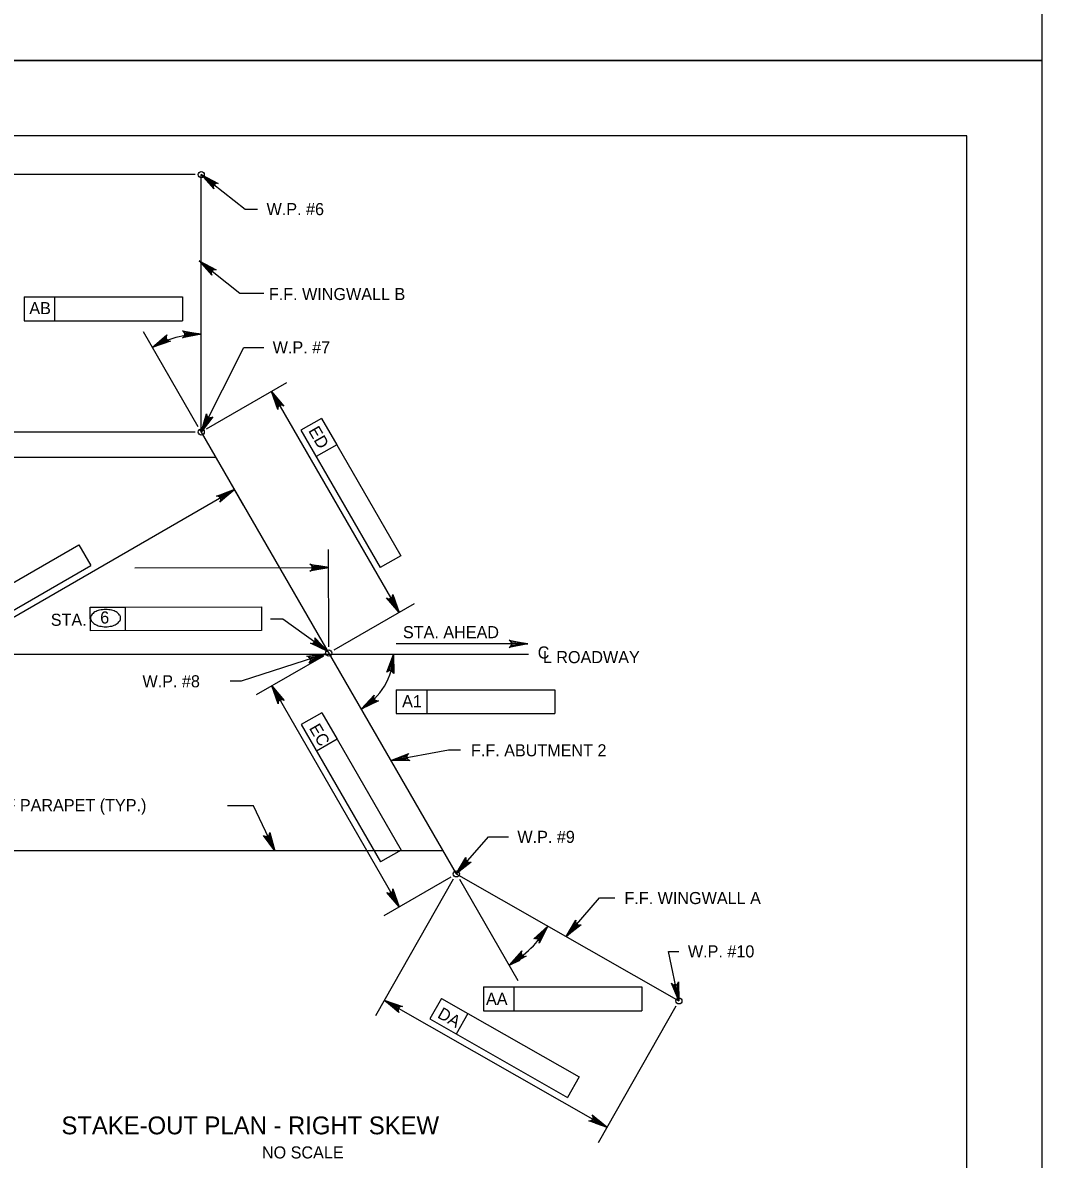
# Model space of a CAD drawing. Extents: x 0 to 36.3, y -66 to 0.
# Drawn here: x 23.87 to 34, y -32.92 to -21.62 of the extents above; entities that cross this region are included whole.
import ezdxf

# ---------------------------------------------------------------- set-up
doc = ezdxf.new("R2010")
doc.units = 0
for name, color, linetype in [('1', 7, 'Continuous'), ('2', 7, 'Continuous'), ('3', 7, 'Continuous'), ('4', 7, 'Continuous'), ('62', 7, 'Continuous'), ('63', 7, 'Continuous')]:
    doc.layers.add(name, color=color, linetype=linetype)

msp = doc.modelspace()

# ---------------------------------------------------------------- linework, layer by layer
at = {"layer": '1'}
msp.add_lwpolyline([(1.75, -43.25), (33.25, -43.25), (33.25, -22.75), (1.75, -22.75)], close=True, dxfattribs=at)
at = {"layer": '2'}
for p, q in [((25.644, -25.693), (25.644, -23.134)), ((25.644, -25.693), (28.178, -30.083)), ((25.791, -25.947), (20.486, -25.947)), ((28.046, -29.854), (21.35, -29.854)), ((28.178, -30.083), (30.39, -31.345))]:
    msp.add_line(p, q, dxfattribs=at)
at = {"layer": '3'}
msp.add_line((28.894, -27.903), (21.637, -27.903), dxfattribs=at)
for centre in [(25.644, -23.134), (25.644, -25.693), (26.911, -27.888), (28.178, -30.083), (30.39, -31.345)]:
    msp.add_circle(centre, 0.0304, dxfattribs=at)
at = {"layer": '4'}
for p, q in [((25.582, -23.134), (23.563, -23.134)), ((23.884, -24.349), (24.187, -24.349)), ((23.884, -24.349), (23.884, -24.586)), ((24.187, -24.349), (24.187, -24.586)), ((24.187, -24.349), (25.459, -24.349)), ((25.459, -24.349), (25.459, -24.586)), ((26.028, -24.312), (26.266, -24.312)), ((23.884, -24.586), (25.459, -24.586)), ((25.613, -25.64), (25.069, -24.697)), ((25.697, -25.662), (26.495, -25.201)), ((26.342, -25.29), (27.609, -27.485)), ((26.839, -25.557), (26.635, -25.675)), ((26.839, -25.557), (26.991, -25.819)), ((25.582, -25.693), (23.563, -25.693)), ((25.625, -25.661), (26.062, -26.418)), ((26.635, -25.675), (27.422, -27.039)), ((26.991, -25.819), (26.786, -25.937)), ((26.991, -25.819), (27.627, -26.921)), ((21.921, -28.605), (25.974, -26.265)), ((23.328, -27.449), (24.429, -26.813)), ((24.429, -26.813), (24.547, -27.017)), ((26.911, -27.826), (26.909, -26.861)), ((27.627, -26.921), (27.422, -27.039)), ((23.184, -27.805), (24.547, -27.017)), ((24.985, -27.042), (26.91, -27.039)), ((24.542, -27.431), (24.891, -27.431)), ((24.543, -27.667), (24.542, -27.431)), ((24.891, -27.431), (26.243, -27.429)), ((24.892, -27.667), (24.891, -27.431)), ((26.243, -27.429), (26.243, -27.666)), ((26.964, -27.857), (27.762, -27.396)), ((26.453, -27.551), (26.333, -27.551)), ((26.902, -27.872), (26.453, -27.551)), ((26.243, -27.666), (24.543, -27.667)), ((28.89, -27.797), (27.579, -27.797)), ((26.858, -27.919), (26.191, -28.304)), ((26.344, -28.215), (27.611, -30.411)), ((27.582, -28.253), (27.884, -28.253)), ((27.582, -28.253), (27.582, -28.489)), ((27.884, -28.253), (27.884, -28.489)), ((27.884, -28.253), (29.156, -28.253)), ((29.156, -28.253), (29.156, -28.489)), ((26.842, -28.482), (26.637, -28.6)), ((26.842, -28.482), (26.993, -28.744)), ((27.582, -28.489), (29.156, -28.489)), ((26.637, -28.6), (27.425, -29.964)), ((26.993, -28.744), (26.788, -28.862)), ((26.993, -28.744), (27.629, -29.846)), ((27.528, -28.956), (28.101, -28.85)), ((28.101, -28.85), (28.221, -28.85)), ((26.163, -29.408), (25.906, -29.408)), ((27.629, -29.846), (27.425, -29.964)), ((28.148, -30.137), (27.375, -31.492)), ((28.125, -30.114), (27.458, -30.499)), ((28.209, -30.136), (28.79, -31.143)), ((29.601, -30.322), (29.753, -30.322)), ((28.447, -31.206), (28.75, -31.206)), ((28.447, -31.206), (28.447, -31.443)), ((28.75, -31.206), (28.75, -31.443)), ((28.75, -31.206), (30.022, -31.206)), ((30.022, -31.206), (30.022, -31.443)), ((27.462, -31.338), (29.674, -32.6)), ((28.032, -31.32), (27.915, -31.525)), ((28.032, -31.32), (28.294, -31.47)), ((28.294, -31.47), (28.177, -31.675)), ((28.294, -31.47), (29.4, -32.101)), ((28.447, -31.443), (30.022, -31.443)), ((30.359, -31.399), (29.586, -32.754)), ((27.915, -31.525), (29.283, -32.306)), ((29.4, -32.101), (29.283, -32.306))]:
    msp.add_line(p, q, dxfattribs=at)
for points in [[(25.644, -23.134), (26.081, -23.477), (26.204, -23.477)], [(25.644, -23.134), (25.812, -23.221), (25.794, -23.22), (25.781, -23.226), (25.772, -23.234), (25.765, -23.245), (25.764, -23.26), (25.769, -23.276), (25.644, -23.134), (25.764, -23.26), (25.765, -23.245), (25.644, -23.134), (25.772, -23.234), (25.781, -23.226), (25.644, -23.134), (25.794, -23.22)], [(25.624, -23.991), (26.028, -24.312)], [(25.624, -23.991), (25.791, -24.08), (25.774, -24.079), (25.76, -24.084), (25.751, -24.092), (25.745, -24.104), (25.743, -24.118), (25.748, -24.135), (25.624, -23.991), (25.743, -24.118), (25.745, -24.104), (25.624, -23.991), (25.751, -24.092), (25.76, -24.084), (25.624, -23.991), (25.774, -24.079)], [(25.158, -24.851), (25.302, -24.727), (25.294, -24.743), (25.294, -24.758), (25.298, -24.77), (25.306, -24.779), (25.319, -24.787), (25.337, -24.788), (25.158, -24.851), (25.319, -24.787), (25.306, -24.779), (25.158, -24.851), (25.298, -24.77), (25.294, -24.758), (25.158, -24.851), (25.294, -24.743)], [(25.644, -24.721), (25.457, -24.756), (25.472, -24.746), (25.479, -24.733), (25.481, -24.721), (25.479, -24.708), (25.472, -24.696), (25.457, -24.686), (25.644, -24.721), (25.472, -24.696), (25.479, -24.708), (25.644, -24.721), (25.481, -24.721), (25.479, -24.733), (25.644, -24.721), (25.472, -24.746)], [(25.644, -25.693), (26.067, -24.851), (26.265, -24.851)], [(26.342, -25.29), (26.465, -25.434), (26.449, -25.426), (26.435, -25.426), (26.423, -25.431), (26.413, -25.439), (26.406, -25.451), (26.405, -25.469), (26.342, -25.29), (26.406, -25.451), (26.413, -25.439), (26.342, -25.29), (26.423, -25.431), (26.435, -25.426), (26.342, -25.29), (26.449, -25.426)], [(25.644, -25.693), (25.696, -25.511), (25.699, -25.528), (25.706, -25.54), (25.717, -25.548), (25.729, -25.551), (25.743, -25.55), (25.759, -25.542), (25.644, -25.693), (25.743, -25.55), (25.729, -25.551), (25.644, -25.693), (25.717, -25.548), (25.706, -25.54), (25.644, -25.693), (25.699, -25.528)], [(25.974, -26.265), (25.83, -26.388), (25.837, -26.372), (25.837, -26.358), (25.833, -26.346), (25.825, -26.336), (25.812, -26.329), (25.795, -26.328), (25.974, -26.265), (25.812, -26.329), (25.825, -26.336), (25.974, -26.265), (25.833, -26.346), (25.837, -26.358), (25.974, -26.265), (25.837, -26.372)], [(26.91, -27.039), (26.723, -27.074), (26.738, -27.064), (26.745, -27.051), (26.747, -27.039), (26.745, -27.026), (26.738, -27.014), (26.723, -27.004), (26.91, -27.039), (26.738, -27.014), (26.745, -27.026), (26.91, -27.039), (26.747, -27.039), (26.745, -27.051), (26.91, -27.039), (26.738, -27.064)], [(27.609, -27.485), (27.485, -27.341), (27.501, -27.349), (27.516, -27.349), (27.528, -27.344), (27.537, -27.336), (27.545, -27.324), (27.546, -27.306), (27.609, -27.485), (27.545, -27.324), (27.537, -27.336), (27.609, -27.485), (27.528, -27.344), (27.516, -27.349), (27.609, -27.485), (27.501, -27.349)], [(26.902, -27.872), (26.73, -27.792), (26.748, -27.793), (26.761, -27.787), (26.77, -27.778), (26.775, -27.767), (26.777, -27.752), (26.771, -27.736), (26.902, -27.872), (26.777, -27.752), (26.775, -27.767), (26.902, -27.872), (26.77, -27.778), (26.761, -27.787), (26.902, -27.872), (26.748, -27.793)], [(28.89, -27.797), (28.704, -27.832), (28.718, -27.822), (28.725, -27.809), (28.727, -27.797), (28.725, -27.784), (28.718, -27.772), (28.704, -27.762), (28.89, -27.797), (28.718, -27.772), (28.725, -27.784), (28.89, -27.797), (28.727, -27.797), (28.725, -27.809), (28.89, -27.797), (28.718, -27.822)], [(26.882, -27.897), (26.039, -28.169), (25.93, -28.169)], [(26.882, -27.897), (26.715, -27.988), (26.726, -27.974), (26.729, -27.96), (26.727, -27.947), (26.722, -27.936), (26.711, -27.927), (26.694, -27.921), (26.882, -27.897), (26.711, -27.927), (26.722, -27.936), (26.882, -27.897), (26.727, -27.947), (26.729, -27.96), (26.882, -27.897), (26.726, -27.974)], [(27.555, -27.903), (27.556, -28.093), (27.549, -28.077), (27.538, -28.067), (27.526, -28.063), (27.513, -28.063), (27.5, -28.068), (27.487, -28.08), (27.555, -27.903), (27.5, -28.068), (27.513, -28.063), (27.555, -27.903), (27.526, -28.063), (27.538, -28.067), (27.555, -27.903), (27.549, -28.077)], [(26.344, -28.215), (26.468, -28.359), (26.452, -28.352), (26.437, -28.352), (26.425, -28.356), (26.416, -28.364), (26.408, -28.377), (26.407, -28.394), (26.344, -28.215), (26.408, -28.377), (26.416, -28.364), (26.344, -28.215), (26.425, -28.356), (26.437, -28.352), (26.344, -28.215), (26.452, -28.352)], [(27.233, -28.446), (27.363, -28.308), (27.357, -28.325), (27.359, -28.339), (27.364, -28.35), (27.374, -28.359), (27.387, -28.365), (27.404, -28.364), (27.233, -28.446), (27.387, -28.365), (27.374, -28.359), (27.233, -28.446), (27.364, -28.35), (27.359, -28.339), (27.233, -28.446), (27.357, -28.325)], [(27.528, -28.956), (27.705, -28.888), (27.692, -28.9), (27.687, -28.914), (27.688, -28.927), (27.692, -28.939), (27.702, -28.95), (27.717, -28.957), (27.528, -28.956), (27.702, -28.95), (27.692, -28.939), (27.528, -28.956), (27.688, -28.927), (27.687, -28.914), (27.528, -28.956), (27.692, -28.9)], [(26.374, -29.854), (26.163, -29.408)], [(26.374, -29.854), (26.263, -29.701), (26.278, -29.709), (26.293, -29.711), (26.305, -29.707), (26.315, -29.7), (26.323, -29.688), (26.326, -29.671), (26.374, -29.854), (26.323, -29.688), (26.315, -29.7), (26.374, -29.854), (26.305, -29.707), (26.293, -29.711), (26.374, -29.854), (26.278, -29.709)], [(28.178, -30.083), (28.498, -29.715), (28.697, -29.715)], [(28.178, -30.083), (28.274, -29.92), (28.272, -29.937), (28.277, -29.951), (28.285, -29.961), (28.296, -29.967), (28.31, -29.97), (28.327, -29.965), (28.178, -30.083), (28.31, -29.97), (28.296, -29.967), (28.178, -30.083), (28.285, -29.961), (28.277, -29.951), (28.178, -30.083), (28.272, -29.937)], [(27.611, -30.411), (27.488, -30.267), (27.504, -30.274), (27.518, -30.274), (27.53, -30.27), (27.54, -30.262), (27.547, -30.249), (27.549, -30.232), (27.611, -30.411), (27.547, -30.249), (27.54, -30.262), (27.611, -30.411), (27.53, -30.27), (27.518, -30.274), (27.611, -30.411), (27.504, -30.274)], [(29.271, -30.706), (29.601, -30.322)], [(29.088, -30.603), (29.003, -30.772), (29.004, -30.754), (28.998, -30.741), (28.99, -30.732), (28.979, -30.726), (28.964, -30.724), (28.948, -30.73), (29.088, -30.603), (28.964, -30.724), (28.979, -30.726), (29.088, -30.603), (28.99, -30.732), (28.998, -30.741), (29.088, -30.603), (29.004, -30.754)], [(29.271, -30.706), (29.366, -30.542), (29.364, -30.56), (29.368, -30.573), (29.377, -30.583), (29.387, -30.59), (29.402, -30.592), (29.419, -30.588), (29.271, -30.706), (29.402, -30.592), (29.387, -30.59), (29.271, -30.706), (29.377, -30.583), (29.368, -30.573), (29.271, -30.706), (29.364, -30.56)], [(28.702, -30.989), (28.828, -30.847), (28.822, -30.864), (28.824, -30.878), (28.83, -30.889), (28.84, -30.898), (28.853, -30.903), (28.871, -30.902), (28.702, -30.989), (28.853, -30.903), (28.84, -30.898), (28.702, -30.989), (28.83, -30.889), (28.824, -30.878), (28.702, -30.989), (28.822, -30.864)], [(30.39, -31.345), (30.286, -30.853), (30.39, -30.853)], [(30.39, -31.345), (30.317, -31.17), (30.33, -31.182), (30.344, -31.187), (30.356, -31.186), (30.368, -31.181), (30.379, -31.172), (30.386, -31.156), (30.39, -31.345), (30.379, -31.172), (30.368, -31.181), (30.39, -31.345), (30.356, -31.186), (30.344, -31.187), (30.39, -31.345), (30.33, -31.182)], [(27.462, -31.338), (27.642, -31.4), (27.624, -31.401), (27.612, -31.409), (27.604, -31.418), (27.599, -31.43), (27.599, -31.445), (27.607, -31.461), (27.462, -31.338), (27.599, -31.445), (27.599, -31.43), (27.462, -31.338), (27.604, -31.418), (27.612, -31.409), (27.462, -31.338), (27.624, -31.401)], [(29.674, -32.6), (29.495, -32.538), (29.512, -32.536), (29.525, -32.529), (29.533, -32.519), (29.537, -32.507), (29.537, -32.493), (29.529, -32.477), (29.674, -32.6), (29.537, -32.493), (29.537, -32.507), (29.674, -32.6), (29.533, -32.519), (29.525, -32.529), (29.674, -32.6), (29.512, -32.536)]]:
    msp.add_lwpolyline(points, dxfattribs=at)
for points in [[(25.644, -23.134), (25.73, -23.214), (25.743, -23.199)], [(25.624, -23.991), (25.71, -24.073), (25.722, -24.057)], [(26.418, -25.382), (26.384, -25.402), (26.342, -25.29)], [(25.644, -25.693), (25.706, -25.592), (25.688, -25.583)], [(25.862, -26.307), (25.881, -26.341), (25.974, -26.265)], [(26.791, -27.019), (26.792, -27.058), (26.91, -27.039)], [(27.567, -27.373), (27.533, -27.393), (27.609, -27.485)], [(26.779, -27.809), (26.802, -27.776), (26.888, -27.862)], [(26.42, -28.308), (26.386, -28.328), (26.344, -28.215)], [(27.664, -28.911), (27.671, -28.95), (27.55, -28.952)], [(26.374, -29.854), (26.333, -29.743), (26.315, -29.752)], [(28.178, -30.083), (28.263, -30), (28.248, -29.988)], [(27.569, -30.299), (27.535, -30.318), (27.611, -30.411)], [(29.271, -30.706), (29.355, -30.623), (29.34, -30.61)], [(28.811, -30.941), (28.79, -30.909), (28.702, -30.99)], [(30.39, -31.345), (30.375, -31.228), (30.356, -31.232)], [(27.575, -31.379), (27.555, -31.414), (27.462, -31.338)], [(29.581, -32.524), (29.562, -32.559), (29.674, -32.6)]]:
    msp.add_lwpolyline(points, close=True, dxfattribs=at)
for centre, radius, start, end in [((25.644, -25.693), 0.972, 89.9992, 119.9991), ((24.595, -27.541), 0.0513, 144.1862, 180), ((24.595, -27.541), 0.0513, 180, 215.8138), ((24.642, -27.575), 0.109, 119.8571, 144.1862), ((24.673, -27.629), 0.172, 103.3749, 119.8571), ((24.694, -27.716), 0.26, 90, 103.3749), ((24.694, -27.716), 0.26, 76.6251, 90), ((24.714, -27.629), 0.172, 60.1429, 76.6251), ((24.745, -27.575), 0.109, 35.8138, 60.1429), ((24.792, -27.541), 0.0513, 0, 35.8138), ((24.792, -27.541), 0.0513, 324.1862, 0), ((24.642, -27.507), 0.109, 215.8138, 240.1429), ((24.673, -27.453), 0.172, 240.1429, 256.6251), ((24.694, -27.367), 0.26, 256.6251, 270), ((24.694, -27.367), 0.26, 270, 283.3749), ((24.714, -27.453), 0.172, 283.3749, 299.8571), ((24.745, -27.507), 0.109, 299.8571, 324.1862), ((26.911, -27.888), 0.644, 300, 358.6476), ((28.178, -30.083), 1.047, 300.0009, 330.2888)]:
    msp.add_arc(centre, radius, start, end, dxfattribs=at)
at = {"layer": '62'}
msp.add_line((34, -22), (34, -22), dxfattribs=at)
at = {"layer": '63'}
for points in [[(0, -22), (34, -22), (34, 0), (0, 0)], [(0, -44), (34, -44), (34, -22), (0, -22)]]:
    msp.add_lwpolyline(points, close=True, dxfattribs=at)

# ---------------------------------------------------------------- texts
at = {"layer": '4'}
for s, height, p in [('W.P. #6', 0.12, (26.293, -23.537)), ('F.F. WINGWALL B', 0.12, (26.316, -24.381)), ('AB', 0.12, (23.936, -24.521)), ('W.P. #7', 0.12, (26.354, -24.911)), ('STA.', 0.12, (24.149, -27.618)), ('STA. AHEAD', 0.12, (27.648, -27.741)), ('C', 0.12, (28.987, -27.943)), ('L ROADWAY', 0.12, (29.038, -27.989)), ('W.P. #8', 0.12, (25.06, -28.229)), ('A1', 0.12, (27.64, -28.427)), ('F.F. ABUTMENT 2', 0.12, (28.324, -28.915)), ('OUTSIDE FACE OF PARAPET (TYP.)', 0.12, (22.344, -29.46)), ('W.P. #9', 0.12, (28.785, -29.775)), ('F.F. WINGWALL A', 0.12, (29.849, -30.383)), ('W.P. #10', 0.12, (30.479, -30.913)), ('AA', 0.12, (28.473, -31.385)), ('STAKE-OUT PLAN - RIGHT SKEW', 0.17717, (24.255, -32.671)), ('NO SCALE', 0.12, (26.247, -32.911))]:
    msp.add_text(s, height=height, dxfattribs=at).set_placement(p)
for s, rotation, p in [('ED', 300, (26.704, -25.678)), ('6', 0.0618, (24.64, -27.595)), ('EC', 300, (26.712, -28.634)), ('DA', 330.2891, (27.982, -31.506))]:
    msp.add_text(s, height=0.12, rotation=rotation, dxfattribs=at).set_placement(p)

doc.saveas('drawing.dxf')
